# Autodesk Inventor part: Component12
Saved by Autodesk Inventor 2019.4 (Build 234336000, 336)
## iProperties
Created: 2020-06
Part Number: Component12
Material: Generic
Document SubType Name: Modeling
Designer: Administrator
Density: 1 g/cm^3
Appearance: Default
Title: Component12
Author: Administrator
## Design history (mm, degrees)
